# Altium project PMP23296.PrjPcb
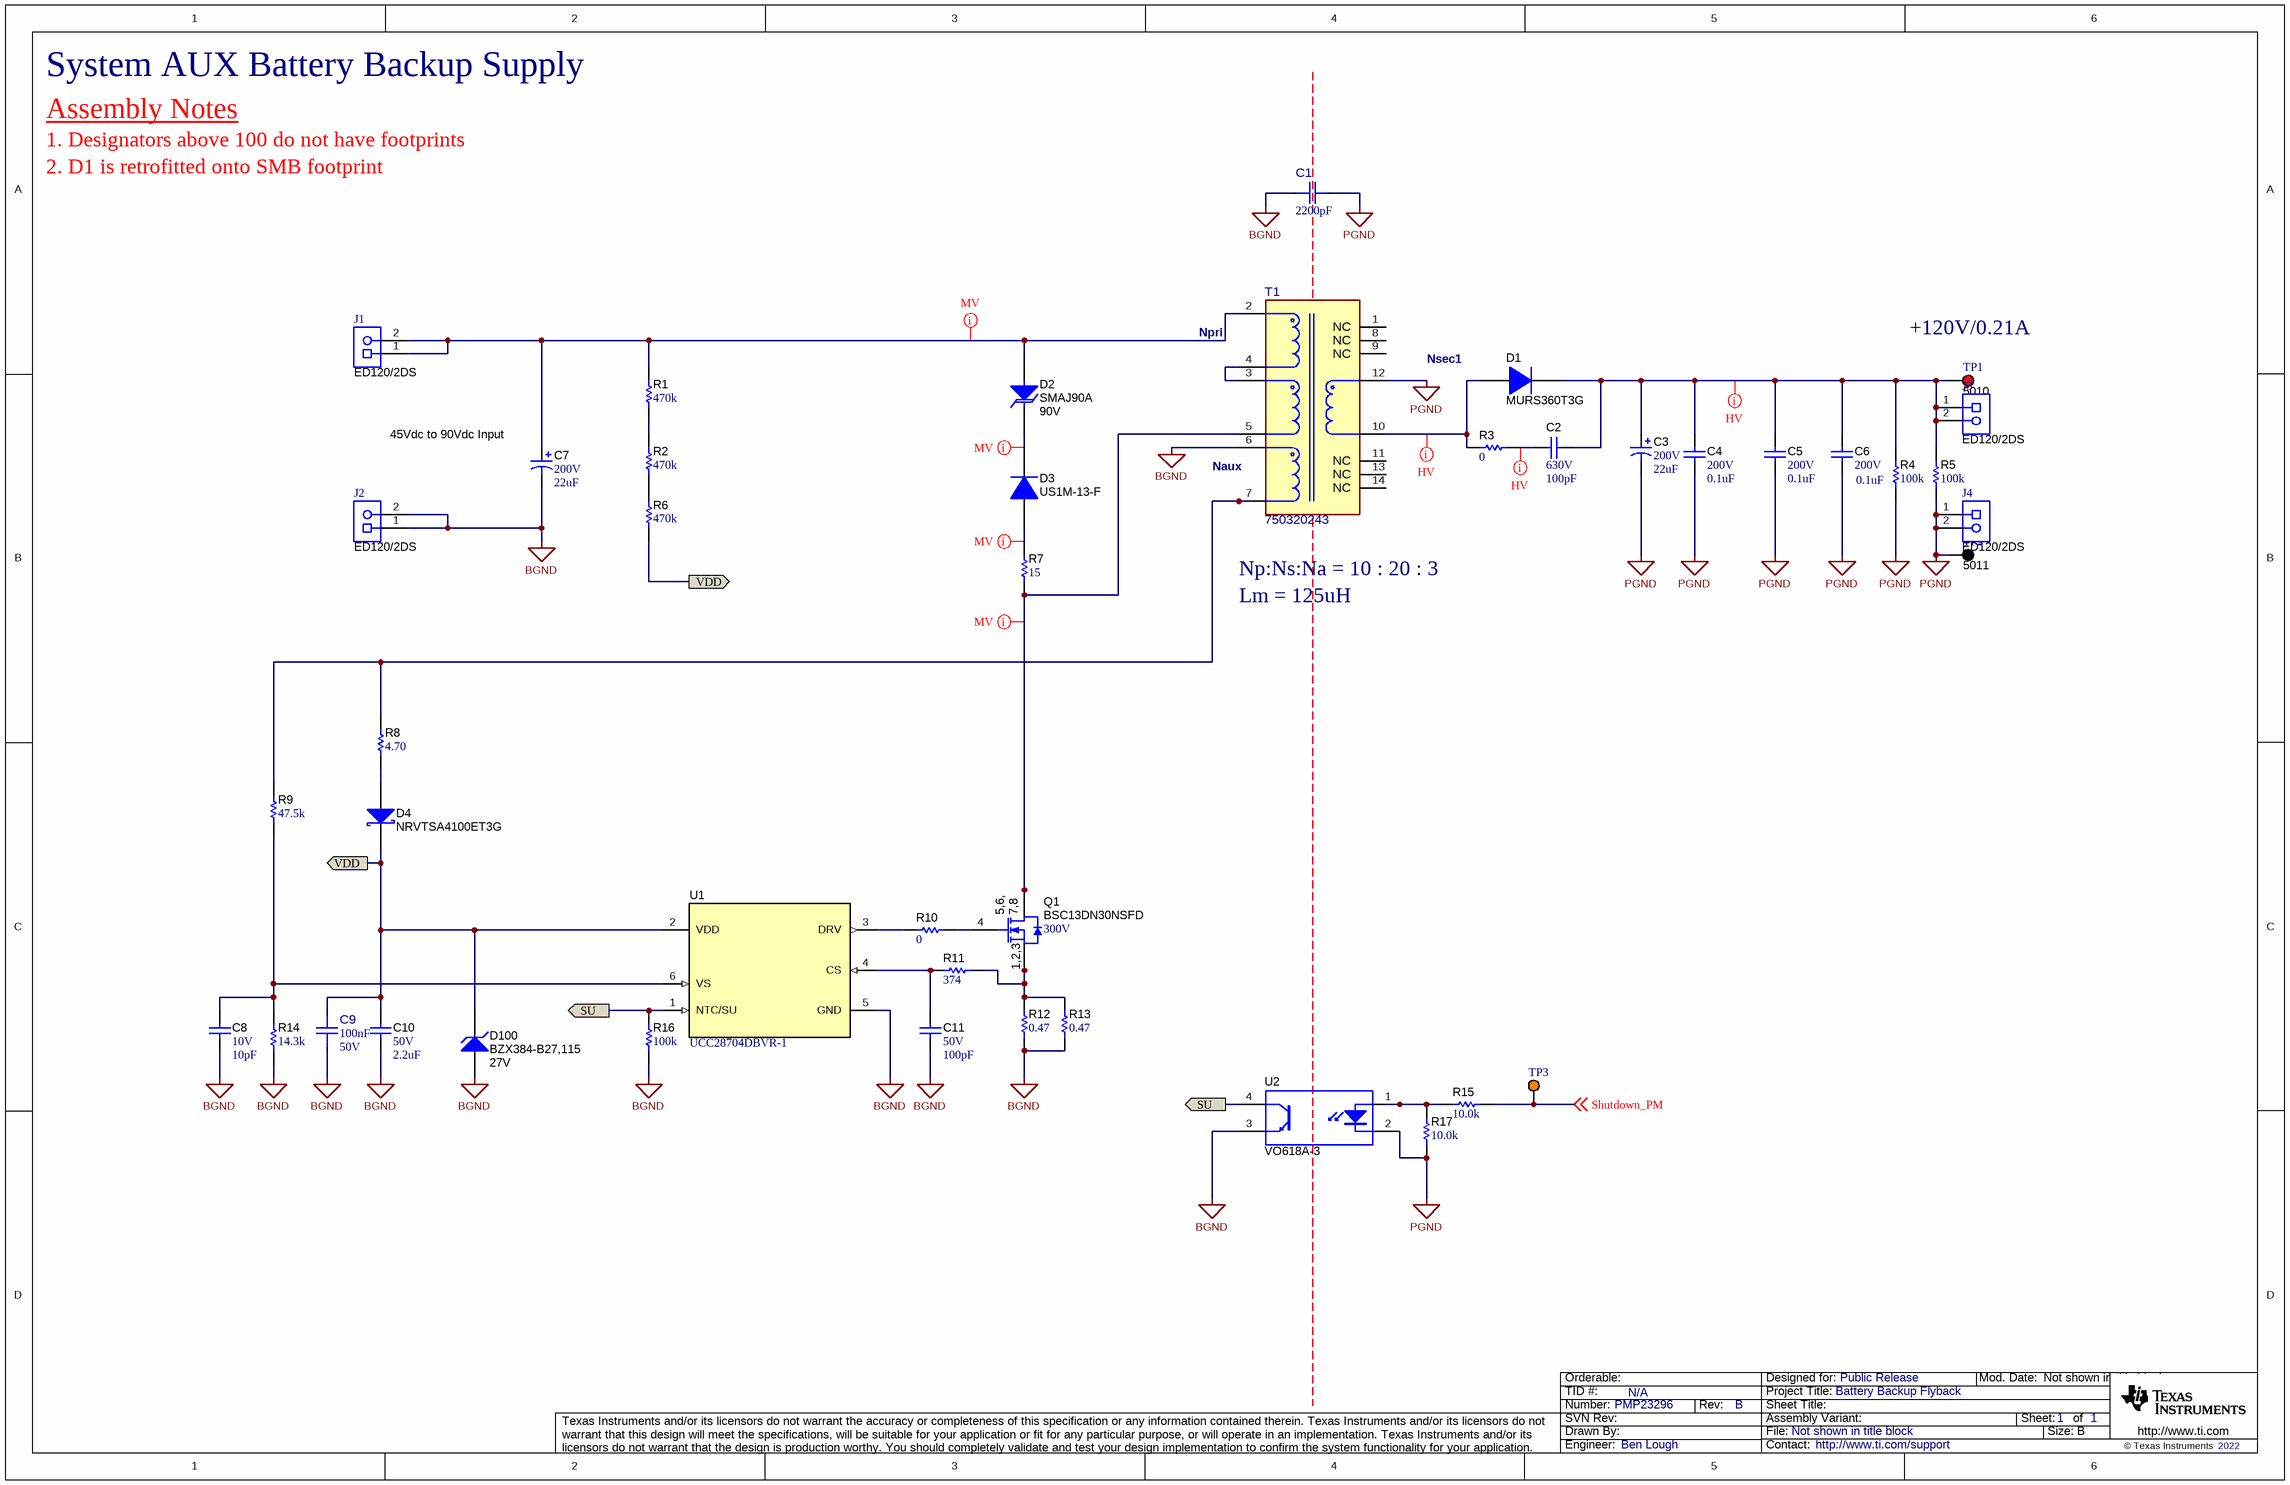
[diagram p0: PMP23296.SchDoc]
TID: N/A; TechSupport: http://www.ti.com/support; SCH_Rev: B; PRJ_Title: Battery Backup Flyback; PRJ_Number: PMP23296; PRJ_Engineer: Ben Lough; PRJ_Customer: Public Release; PCB_Rev: A; PCB_Layout: Ben Lough; CopyrightYear: 2022
1 sheet, 44 parts. Net scope: flat (ports and power ports of the same name join across sheets).
Board file: PMP23296.PcbDoc

## Sheet PMP23296.SchDoc
size 431 x 279 mm; Date: Not shown in title block; ApprovedBy: Not shown in title block; CheckedBy: Not shown in title block; Author: Not shown in title block; CompanyName: Not shown in title block; Engineer: Not shown in title block; Organization: Not shown in title block; Address1: Not shown in title block; Address2: Not shown in title block; Address3: Not shown in title block; Address4: Not shown in title block; DocumentNumber: 1; Revision: Use project parameter SCH_Rev; SheetNumber: 1; SheetTotal: 1; PageSetup: Record=PageOptions¦CenterHorizontal=True¦CenterVertical=True¦PrintScale=1.00¦XCorrection=1.00¦YCorrection=1.00¦PrintKind=0¦BorderSize=5000000¦LeftOffset=0¦BottomOffset=0¦Orientation=2¦PaperLength=1000¦PaperWidth=1000¦Scale=100¦PaperSource=15¦PrintQuality=600¦MediaType=1¦DitherType=10¦PaperKind=Letter¦PrintScaleMode=1

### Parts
C1  ValueDisplayed: 2200pF  [FP-DE2E3KY222MN2AM01F_RADIAL-MFG]  (hidden comment: DE2E3KY222MN2AM01F)
C2  VDC_V: 630V  ValueDisplayed: 100pF  [1206]  (hidden comment: GRM31A5C2J101JW01D)
C3  VDC_V: 200V  ValueDisplayed: 22uF  [CA_1000x2000]  (hidden comment: UCA2D220MPD1TD)
C4  VDC_V: 200V  ValueDisplayed: 0.1uF  [1206]  (hidden comment: C1206C104K2RACTU)
C5  VDC_V: 200V  ValueDisplayed: 0.1uF  [1206]  (hidden comment: C1206C104K2RACTU)
C6  VDC_V: 200V  ValueDisplayed: 0.1uF  [1206]  (hidden comment: C1206C104K2RACTU)
C7  VDC_V: 200V  ValueDisplayed: 22uF  [UPW_1000x2000]  (hidden comment: UPW2D220MPD1TD)
C8  VDC_V: 10V  ValueDisplayed: 10pF  [0402]  (hidden comment: C0402C100C8GACTU)
C9  Cap_F: 100nF  VDC_V: 50V  [FP-06035C104J4Z2A_0603-MFG]  (hidden comment: 06035C104J4Z2A)
C10  VDC_V: 50V  ValueDisplayed: 2.2uF  [1206_180]  (hidden comment: C3216X5R1H225K160AB)
C11  VDC_V: 50V  ValueDisplayed: 100pF  [0402]  (hidden comment: CC0402KRX7R9BB101)
D1  MURS360T3G  [SMC]
D2  SMAJ90A  value 90V  [SMA]
D3  US1M-13-F  [SMA]
D4  NRVTSA4100ET3G  [SMA]
D100  BZX384-B27,115  value 27V  [SOD-323]
J1  ED120/2DS  [On-Shore_ED120_2DS]
J2  ED120/2DS  [On-Shore_ED120_2DS]
J3  ED120/2DS  [On-Shore_ED120_2DS]
J4  ED120/2DS  [On-Shore_ED120_2DS]
Q1  BSC13DN30NSFD  value 300V  [PG-TDSON-8]
R1  ValueDisplayed: 470k  [1206]  (hidden comment: RC1206FR-07470KL)
R2  ValueDisplayed: 470k  [1206]  (hidden comment: RC1206FR-07470KL)
R3  ValueDisplayed: 0  [1206]  (hidden comment: ERJ-8GEY0R00V)
R4  ValueDisplayed: 100k  [1206]  (hidden comment: RC1206FR-07100KL)
R5  ValueDisplayed: 100k  [1206]  (hidden comment: RC1206FR-07100KL)
R6  ValueDisplayed: 470k  [1206]  (hidden comment: RC1206FR-07470KL)
R7  ValueDisplayed: 15  [1206]  (hidden comment: CRCW120615R0JNEA)
R8  ValueDisplayed: 4.70  [1206]  (hidden comment: RC1206FR-074R7L)
R9  ValueDisplayed: 47.5k  [0603]  (hidden comment: RC0603FR-0747K5L)
R10  ValueDisplayed: 0  [0603]  (hidden comment: ERJ-3GEY0R00V)
R11  ValueDisplayed: 374  [0603]  (hidden comment: RC0603FR-07374RL)
R12  ValueDisplayed: 0.47  [1206]  (hidden comment: ERJ-8RQFR47V)
R13  ValueDisplayed: 0.47  [1206]  (hidden comment: ERJ-8RQFR47V)
R14  ValueDisplayed: 14.3k  [0603]  (hidden comment: RC0603FR-0714K3L)
R15  ValueDisplayed: 10.0k  [0603]  (hidden comment: M55342K12B10E0T)
R16  ValueDisplayed: 100k  [0402]  (hidden comment: RC0402FR-07100KL)
R17  ValueDisplayed: 10.0k  [0603]  (hidden comment: M55342K12B10E0T)
T1  750320243  [FP-750320243_PTH14_32MM25_27MM05-MFG]
TP1  5010  [Keystone5010]
TP2  5011  [Keystone5011]
TP3  5013  [Keystone5013]  (value not drawn)
U1  UCC28704DBVR-1  [DBV0006A_N]
U2  VO618A-3  [DIP-4]

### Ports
SU (out), VDD (out)

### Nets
BGND: C1.1 C7.2(-) C8.2 C9.1 C10.2 C11.2 D100.2(A) J2.1 J2.2 R12.1 R13.1 R14.1 R16.1 T1.6 U1.5(GND) U2.3(E)
PGND: C1.2 C3.2(-) C4.2 C5.2 C6.2 J4.1 J4.2 R4.1 R5.1 R17.1 T1.12 TP2.1 U2.2(K)
Shutdown_PM: R15.2 TP3.1 ; off-sheet Shutdown_PM
SU: R16.2 U1.1(NTC/SU) U2.4(C) ; port SU
VDD: C9.2 C10.1 D4.1(K) D100.1(K) R6.1 U1.2(VDD) ; port VDD
NetC2_1: C2.1 C3.1(+) C4.1 C5.1 C6.1 D1.1(K) J3.1 J3.2 R4.2 R5.2 TP1.1
NetC2_2: C2.2 R3.2
NetC7_1: C7.1(+) D2.2(A) J1.1 J1.2 R1.2 T1.2
NetC8_1: C8.1 R9.1 R14.2 U1.6(VS)
NetC11_1: C11.1 R11.1 U1.4(CS)
NetD1_2: D1.2(A) R3.1 T1.10
NetD2_1: D2.1(K) D3.1(K)
NetD3_2: D3.2(A) R7.2
NetD4_2: D4.2(A) R8.1
NetQ1_1: Q1.1(S) Q1.2(S) Q1.3(S) R11.2 R12.2 R13.2
NetQ1_4: Q1.4(G) R10.2
NetQ1_5: Q1.5(D) Q1.6(D) Q1.7(D) Q1.8(D) Q1.9(D) R7.1 T1.5
NetR1_1: R1.1 R2.2
NetR2_1: R2.1 R6.2
NetR8_2: R8.2 R9.2 T1.7
NetR10_1: R10.1 U1.3(DRV)
NetR15_1: R15.1 R17.2 U2.1(A)
NetT1_3: T1.3 T1.4

Not connected (* = marked no-connect by the designer): T1 1(NC) 8(NC) 9(NC) 11(NC) 13(NC) 14(NC)

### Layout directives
net class HV: NetC2_1, NetC2_2, NetD1_2
net class MV: NetC7_1, NetD2_1, NetD3_2, NetQ1_5

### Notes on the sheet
- System AUX Battery Backup Supply
- Assembly Notes
- 1. Designators above 100 do not have footprints
- 2. D1 is retrofitted onto SMB footprint
- (near T1) Npri
- Nsec1
- (near TP1) +120V/0.21A
- (near C7) 45Vdc to 90Vdc Input
- (near T1) Naux
- Np:Ns:Na = 10 : 20 : 3
- Lm = 125uH

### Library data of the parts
C1 = CMP-0095357-1: Cap Ceramic Single Suppression X1/Y2 0.0022uF 250VAC E 20% (8 X 5mm) Radial Disc 5mm 125C Ammo; Manufacturer: Murata; Cap_F: 2.2nF; Voltage Ac Rating X: 250V; AEC Qualified: No; TempCo: +20/-55%; Value: 2.2nF; SizeZ_mm: 11mm
C2 = CMP-0008884-2: CAP, CERM, 100 pF, 630 V, +/- 5%, C0G/NP0, 1206; Manufacturer: MuRata; TaMin_C: -55°C; Polarized: N; SizeAreaWB_mm2: 10.92; Value1: Unknown; U/M: EA; Value: 100pF; TaMax_C: 125°C; SizeZ_mm: 1.35; SizeX_mm: 3.2; SizeY_mm: 1.6; SizeArea_mm2: 5.12; AEC Category: Q200
C3 = CMP-0010235-2: CAP, AL, 22 uF, 200 V, +/- 20%, TH; Manufacturer: Nichicon; TaMin_C: -25°C; Polarized: Y; SizeAreaWB_mm2: 144; Value1: Unknown; U/M: EA; Value: 22uF; TaMax_C: 105°C; SizeZ_mm: 21.5; SizeX_mm: 10; Cap_Case: 10x20mm; SizeArea_mm2: 100; CompType: Capacitor; AEC Qualified: N; Cap_F: 22µF; IRMS_A: 500mA; AEC Category: Q200
C4-C6 = CMP-0008585-2: CAP, CERM, 0.1 uF, 200 V, +/- 10%, X7R, 1206; Manufacturer: Kemet; TaMin_C: -55°C; Polarized: N; SizeAreaWB_mm2: 10.92; Value1: Unknown; U/M: EA; Value: 0.1uF; TaMax_C: 125°C; SizeZ_mm: 1.35; SizeX_mm: 3.2; SizeY_mm: 1.6; SizeArea_mm2: 5.12; Cap_F: 100nF; AEC Category: Q200
C7 = CMP-0064890-1: CAP, AL, 22 uF, 200 V, +/- 20%, TH; Manufacturer: Nichicon; TaMin_C: -40°C; Polarized: Y; SizeAreaWB_mm2: 144; Value1: Unknown; U/M: EA; Value: 22uF; TaMax_C: 105°C; SizeZ_mm: 22; SizeX_mm: 10; Cap_Case: 10x20mm; SizeArea_mm2: 100; CompType: Capacitor; AEC Qualified: N; Cap_F: 22µF; IRMS_A: 1.4dA; AEC Category: Q200
C8 = CMP-0064914-2: CAP, CERM, 10 pF, 10 V,+/- 2.5%, C0G/NP0, 0402; Manufacturer: Kemet; TaMin_C: -55°C; Polarized: N; SizeAreaWB_mm2: 3; Value1: Unknown; U/M: EA; Value: 10pF; TaMax_C: 125°C; SizeZ_mm: 0.6; SizeX_mm: 1; SizeY_mm: 0.5; AEC Category: Q200
C9 = CMP-0094511-1: 0.1 µF ±5% 50V Ceramic Capacitor X7R 0603 (1608 Metric); Manufacturer: KYOCERA AVX; AEC Qualified: Yes; AEC Grade: NA; ValueDisplayed: 0.1uF; Value: 100nF; TempCo: 15%; SizeZ_mm: 0.9mm
C10 = CMP-0008660-2: CAP, CERM, 2.2 uF, 50 V, +/- 10%, X5R, 1206; Manufacturer: TDK; TaMin_C: -55°C; ESR_ohm: 5.887m; Polarized: N; SizeAreaWB_mm2: 10.92; Value1: 0.005887 ohm; U/M: EA; Value: 2.2uF; TaMax_C: 85°C; SizeZ_mm: 1.8; SizeX_mm: 3.2; SizeY_mm: 1.6; SizeArea_mm2: 5.12; Cap_F: 2.2µF; IRMS_A: 2.99226A; AEC Category: Q200
C11 = CMP-0006305-2: CAP, CERM, 100 pF, 50 V, +/- 10%, X7R, 0402; Manufacturer: Yageo America; TaMin_C: -55°C; Polarized: N; SizeAreaWB_mm2: 3; Value1: Unknown; U/M: EA; Value: 100pF; TaMax_C: 125°C; SizeZ_mm: 0.6; SizeX_mm: 1; SizeY_mm: 0.5; AEC Category: Q200
D1 = CMP-0076905-2: Diode, Ultrafast, 600 V, 3 A, SMC; Manufacturer: ON Semiconductor; TJmax_C: 175°C; SizeAreaWB_mm2: 83.2686; Vr_V: 600V; SizeZ_mm: 2.6; SizeArea_mm2: 50.5686; Io_A: 3A; SizeY_mm: 6.22; Value: 600V; SizeX_mm: 8.13; RJC_CperW: 11.0; Value2: 1.25V; Green_REACh: Passed; Green_Lifecycle: Active; AEC Category: Q101
D2 = CMP-0084977-1: Diode, TVS, Uni, 90 V, 146 Vc, 400 W, 2.7 A, SMA; Manufacturer: Littelfuse; RJA_CperW: 120; Vbr_Max: 111V; SizeAreaWB_mm2: 37.3428; SizeY_mm: 2.92; SizeX_mm: 5.59; AEC Category: Q101; Green_REACh: Incomplete; SizeArea_mm2: 16.3228; SizeZ_mm: 2.87; Green_Lifecycle: Active; Vc: 146V; Vbr_Min: 100V; Ipp: 2.7A; Ppk: 400W; AEC Qualified: N
D3 = CMP-0076882-2: Diode, Ultrafast, 1000 V, 1 A, SMA; Manufacturer: Diodes Inc.; AEC Category: Q101; Value2: 1.7V; SizeZ_mm: 2.87; Green_REACh: Incomplete; Value: 1000V; Value1: 1A; SizeAreaWB_mm2: 37.3428; Green_Lifecycle: Not Set; RJC_CperW: 30.0; SizeX_mm: 5.59; SizeArea_mm2: 16.3228; Vr_V: 1kV; TJmax_C: 150°C; SizeY_mm: 2.92
D4 = CMP-0081057-2: Diode, Schottky, 100 V, 4 A, AEC-Q101, SMA; Manufacturer: ON Semiconductor; SizeZ_mm: 2.87; SizeY_mm: 2.92; SizeAreaWB_mm2: 37.3428; Io_A: 4A; AEC Category: Q101; SizeX_mm: 5.59; Value: 100V; SizeArea_mm2: 16.3228; Value2: 0.68V; TJmax_C: 175°C; AEC Qualified: Y; Vf_V: 680mV
D100 = CMP-0005842-4: Diode, Zener, 27 V, 300 mW, SOD-323; Manufacturer: NXP Semiconductor; Power_W: 300mW; SizeArea_mm2: 3.645; RJA_CperW: 415; AEC Category: Q101; Value1: 0.3W; SizeY_mm: 1.35; SizeZ_mm: 1; SizeX_mm: 2.7; SizeAreaWB_mm2: 8.695
J1-J4 = CMP-0074910-1: Terminal Block, 5.08 mm, 2x1, Brass, TH; Manufacturer: On-Shore Technology; Cert_VDE: Y; CNHeader: False; Current_A: 15A; Green_Lifecycle: Not Set; Shrouded: N; Gender: Female; Green_REACh: Incomplete; Voltage_V: 300V; Row_Count: 1; Pitch_mm: 5.08; CT: True
Q1 = CMP-0000907-1: MOSFET, N-CH, 300 V, 16 A, PG-TDSON-8; Alternate Manufacturer: None; Manufacturer: Infineon Technologies; SizeZ_mm: 1.12; ChType: N; SizeX_mm: 5.99; SizeY_mm: 4.9; Vgs_V: 20V; SizeArea_mm2: 29.351; IdsMax_A: 16A; SizeAreaWB_mm2: 55.131; U/M: EA; QgTyp_nC: 23
R1 R2 R6 = CMP-0018313-2: RES, 470 k, 1%, 0.25 W, 1206; Manufacturer: Yageo America; Power_W: 250mW; TempCo: 100 ppm/C; U/M: EA; Value: 470k; SizeX_mm: 3.2; SizeY_mm: 1.6; SizeZ_mm: 1.35; Value2: 0.25W; SizeArea_mm2: 5.12; VDC_V: 200V; AEC Category: Q200
R3 = CMP-0018748-3: RES, 0, 5%, 0.25 W, AEC-Q200 Grade 0, 1206; Manufacturer: Panasonic; Power_W: 250mW; TempCo: 600 ppm/C; Value_Code: 0000; Value: 0; EIA_Code: E24; SizeX_mm: 3.2; SizeY_mm: 1.6; SizeZ_mm: 1.35; Value2: 0.25W; SizeArea_mm2: 5.12; AEC Qualified: Y; VDC_V: 200V; AEC Category: Q200; SizeAreaWB_mm2: 10.92
R4 R5 = CMP-0017836-2: RES, 100 k, 1%, 0.25 W, 1206; Manufacturer: Yageo America; Power_W: 250mW; TempCo: 100 ppm/C; U/M: EA; Value: 100k; EIA_Code: E96; SizeX_mm: 3.2; SizeY_mm: 1.6; SizeZ_mm: 1.35; Value2: 0.25W; SizeArea_mm2: 5.12; VDC_V: 200V; AEC Category: Q200
R7 = CMP-0018594-3: RES, 15, 5%, 0.25 W, AEC-Q200 Grade 0, 1206; Manufacturer: Vishay-Dale; Power_W: 250mW; TempCo: 200 ppm/C; Value_Code: 15R0; Value: 15; EIA_Code: E24; SizeX_mm: 3.2; SizeY_mm: 1.6; SizeZ_mm: 1.35; Value2: 0.25W; SizeArea_mm2: 5.12; AEC Qualified: Y; VDC_V: 200V; AEC Category: Q200; AEC Grade: 0
R8 = CMP-0018350-2: RES, 4.70, 1%, 0.25 W, 1206; Manufacturer: Yageo America; Power_W: 250mW; TempCo: 200 ppm/C; Value_Code: 4R70; U/M: EA; Value: 4.70; Res_ohm: 4.7; SizeX_mm: 3.2; SizeY_mm: 1.6; SizeZ_mm: 1.35; Value2: 0.25W; SizeArea_mm2: 5.12; VDC_V: 200V; AEC Category: Q200
R9 = CMP-0023132-5: RES, 47.5 k, 1%, 0.1 W, 0603; Manufacturer: Yageo; Power_W: 100mW; TempCo: 100 ppm/C; Value_Code: 47k5; Value: 47.5k; EIA_Code: E96; SizeX_mm: 1.6; SizeY_mm: 0.8; SizeZ_mm: 1; Value2: 0.1W; SizeArea_mm2: 1.28; AEC Qualified: N; VDC_V: 75V; AEC Category: Q200; SizeAreaWB_mm2: 4.68
R10 = CMP-0025874-2: RES, 0, 5%, 0.1 W, 0603; Manufacturer: Panasonic; Power_W: 100mW; TempCo: 600 ppm/C; Value_Code: 0000; U/M: EA; Value: 0; EIA_Code: E24; SizeX_mm: 1.6; SizeY_mm: 0.8; SizeZ_mm: 1; Value2: 0.1W; SizeArea_mm2: 1.28; VDC_V: 50V; AEC Category: Q200
R11 = CMP-0023061-5: RES, 374, 1%, 0.1 W, 0603; Manufacturer: Yageo; Power_W: 100mW; TempCo: 100 ppm/C; Value_Code: 374R; Value: 374; EIA_Code: E96; SizeX_mm: 1.6; SizeY_mm: 0.8; SizeZ_mm: 1; Value2: 0.1W; SizeArea_mm2: 1.28; AEC Qualified: N; VDC_V: 75V; AEC Category: Q200; SizeAreaWB_mm2: 4.68
R12 R13 = CMP-0017791-3: RES, 0.47, 1%, 0.25 W, AEC-Q200 Grade 0, 1206; Manufacturer: Panasonic; Power_W: 250mW; TempCo: 250 ppm/C; Value_Code: R470; Value: 0.47; EIA_Code: E96; SizeX_mm: 3.2; SizeY_mm: 1.6; SizeZ_mm: 1.35; Value2: 0.25W; SizeArea_mm2: 5.12; AEC Qualified: Y; AEC Category: Q200; AEC Grade: 0; SizeAreaWB_mm2: 10.92
R14 = CMP-0022802-5: RES, 14.3 k, 1%, 0.1 W, 0603; Manufacturer: Yageo; Power_W: 100mW; TempCo: 100 ppm/C; Value_Code: 14k3; Value: 14.3k; EIA_Code: E96; SizeX_mm: 1.6; SizeY_mm: 0.8; SizeZ_mm: 1; Value2: 0.1W; SizeArea_mm2: 1.28; AEC Qualified: N; VDC_V: 75V; AEC Category: Q200; SizeAreaWB_mm2: 4.68
R15 R17 = CMP-0080488-1: RES, 10.0 k, 1%, 0.1 W, 0603; Manufacturer: TT Electronics/IRC; Power_W: 100mW; TempCo: 100 ppm/C; SizeAreaWB_mm2: 4.68; Value_Code: 10k0; Value: 10.0k; EIA_Code: E96; Res_ohm: 10k; SizeX_mm: 1.6; SizeY_mm: 0.8; SizeZ_mm: 1; Value2: 0.1W; SizeArea_mm2: 1.28; AEC Qualified: N; AEC Category: Q200
R16 = CMP-0026721-1: RES, 100 k, 1%, 0.0625 W, 0402; Manufacturer: Yageo America; Power_W: 62.5mW; TempCo: 100 ppm/C; U/M: EA; Value: 100k; EIA_Code: E96; SizeX_mm: 1; SizeY_mm: 0.5; SizeZ_mm: 0.6; AEC Qualified: N; VDC_V: 50V; AEC Category: Q200
T1 = CMP-0096302-1: TRANSFORMER; Manufacturer: Wurth Electronics; Frequency_Fixed: 25-85kHz; AEC Qualified: No; Voltage_Isolation_Vrms: 2.85kV; DCR_ohm: 0.18; Rsec1_ohm: 0.87; SizeZ_mm: 22.86mm; Ind_H: 125µH; Ns1toNp: 1:2
TP1 = CMP-0055147-2: Test Point, Multipurpose, Red, TH; Manufacturer: Keystone Electronics; CT: TRUE; ContactFinish: Silver; Green_Lifecycle: Active; CNHeader: FALSE; Green_REACh: Passed
TP2 = CMP-0055148-2: Test Point, Multipurpose, Black, TH; Manufacturer: Keystone Electronics; CNHeader: FALSE; ContactFinish: Silver; Green_REACh: Passed; Green_Lifecycle: Active; CT: TRUE
TP3 = CMP-0055150-2: Test Point, Multipurpose, Orange, TH; Manufacturer: Keystone Electronics; CT: TRUE; ContactFinish: Silver; Green_REACh: Passed; CNHeader: FALSE; Green_Lifecycle: Active
U1 = CMP-0074087-1: Off-Line Constant-Voltage Constant-Current Flyback Controller With Primary-Side Regulation (PSR), DBV0006A (SOT-23-6); Alternate PartNumber: UCC28704DBVT-1; Alternate Manufacturer: Texas Instruments; Green_Lifecycle: Active; SizeAreaWB_mm2: 14.82; Green_REACh: Passed; U/M: EA; SizeZ_mm: 1.45; SizeX_mm: 2.8; SizeY_mm: 2.9; SizeArea_mm2: 8.12; CompType: IC
U2 = CMP-0083653-1: Optocoupler, 5.3 kV, 100-200% CTR, SMT; Manufacturer: Vishay-Semiconductor; CTR (Max): 200%; SizeAreaWB_mm2: 71.064; CTR (Min): 100%; SizeZ_mm: 5; SizeX_mm: 8.8; SizeY_mm: 4.58; SizeArea_mm2: 40.304; Voltage_Isolation_Vrms: 5.3kV

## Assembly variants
001: not fitted C8 R5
